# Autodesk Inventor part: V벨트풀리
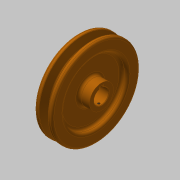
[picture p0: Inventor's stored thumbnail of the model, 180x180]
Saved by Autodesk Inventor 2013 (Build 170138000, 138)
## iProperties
Created: 2015-11
Part Number: V벨트풀리
Material: 강철, 탄소
Document SubType Name: Modeling
Designer: mduedu
Density: 1 g/cm^3
Author: mduedu
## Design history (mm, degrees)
sketch "스케치1"
  geometry: L1 (-9.5, 0)-(9.5, 0); L2 (0, 0)-(0, 47.7); L3 (-4.877, 47.7)-(-9.5, 47.7); L4 (-9.5, 47.7)-(-9.5, 0); L5 (0, 38.7)-(-1.953, 38.7); L6 (-1.953, 38.7)-(-4.877, 47.7); L7 (4.877, 47.7)-(9.5, 47.7); L8 (9.5, 47.7)-(9.5, 0); L9 (0, 38.7)-(1.953, 38.7); L10 (1.953, 38.7)-(4.877, 47.7); L11 (-9.5, 45)-(9.5, 45); 3 further points
  constraints: 22 end point, 7 point on line, 4 perpendicular, 3 symmetric about line, 1 coincident, 1 horizontal, 1 horizontal alignment, 1 midpoint, 1 vertical
  dimensions: "d0" = 19 distance of L1.start L1.end; "d2" = 95.4 diameter of L2.end L1 (derived); "d3" = 36 deg angle of L10 L6; "d4" = 6.3 distance between parallel lines of L11 L9; "d5" = 2.7 distance between parallel lines of L7 L11; "d6" = 8 distance of point (4, 45) point (-4, 45); "d7" = 90 diameter of L11 L1
revolve "회전1" sketch "스케치1" stored, may be unused: angle "d8" = 90 deg
sketch "스케치2"
  geometry: C1 r 34 at (0, 0); C2 r 13 at (0, 0); 1 further point
  constraints: 2 centre point, 2 coincident
  dimensions: "d9" = 68 diameter of C1; "d10" = 26 diameter of C2
extrude "돌출1" cut sketch "스케치2" distance "d11" = 6; taper "d12" = 0 deg
extrude "돌출3" join sketch "스케치2" distance "d37" = 6; taper "d38" = 0 deg
fillet "모깎기1" dims "d13" = 3
fillet "모깎기2" dims "d14" = 3
fillet "모깎기3" dims "d15" = 1, "d16" = 0.5, "d17" = 2
hole "구멍1" diameter "d20" = 16; stored, may be unused: countersink angle "d24" = 90 deg, drill point angle "d26" = 118 deg; dims "d21" = 6, "d22" = 4, "d23" = 2, "d25" = 8, "d53" = 10, "d54" = 10
sketch "스케치3"
  geometry: L1 (-2.5, 0)-(2.5, 0); L2 (2.5, 0)-(2.5, 10.3); L3 (2.5, 10.3)-(-2.5, 10.3); L4 (-2.5, 10.3)-(-2.5, 0); 2 further points
  constraints: 8 end point, 2 parallel, 1 coincident, 1 horizontal, 1 midpoint, 1 perpendicular
  dimensions: "d27" = 5 distance of L2.end L3.end; "d29" = 10.3 distance of L3.end L1.start
extrude "돌출2" cut sketch "스케치3" stored distance "d30" = 6; taper "d31" = 0 deg
node "작업 평면1"
sketch "스케치4"
  geometry: L1 (19, -37)-(19, 37) reference; 2 further points
  constraints: 1 horizontal alignment
  dimensions: "d52" = 22 distance from line of L1 point (-3, 0)
hole "구멍2" sketch "스케치4" at (-3, 0) diameter "d42" = 2.459; stored, may be unused: countersink angle "d46" = 90 deg, drill point angle "d48" = 118 deg; dims "d43" = 6, "d44" = 4, "d45" = 2, "d47" = 8
chamfer "모따기3" distance "d58" = 0.5; stored, may be unused: second distance "d59" = 2, angle "d60" = 45 deg
node "솔리드1"
mirror "대칭1"
